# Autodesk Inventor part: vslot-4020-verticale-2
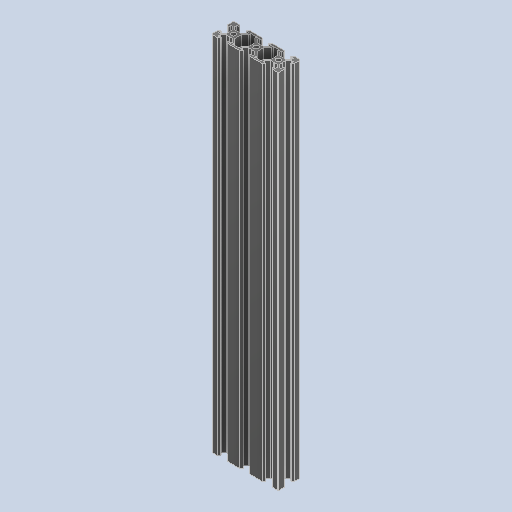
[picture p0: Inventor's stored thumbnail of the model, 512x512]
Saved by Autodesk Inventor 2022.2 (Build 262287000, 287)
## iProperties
Created: 2024-10
Part Number: vslot-4020-verticale-2
Material: Alluminio 6061
Document SubType Name: Modeling
Designer: 18907419
Density: 2.7 g/cm^3
Appearance: Default
Author: 18907419
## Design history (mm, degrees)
feature "Solido47"
node "Solido1"
